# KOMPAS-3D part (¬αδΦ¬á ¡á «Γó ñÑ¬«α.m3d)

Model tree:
1. Эскиз:2
2. Операция выдавливания:2
     Расстояние 1 = 2
3. Эскиз:3
4. Вырезать элемент выдавливания:1
     Расстояние 1 = 10
5. Эскиз:4
6. Операция выдавливания:3
     Расстояние 1 = 13
